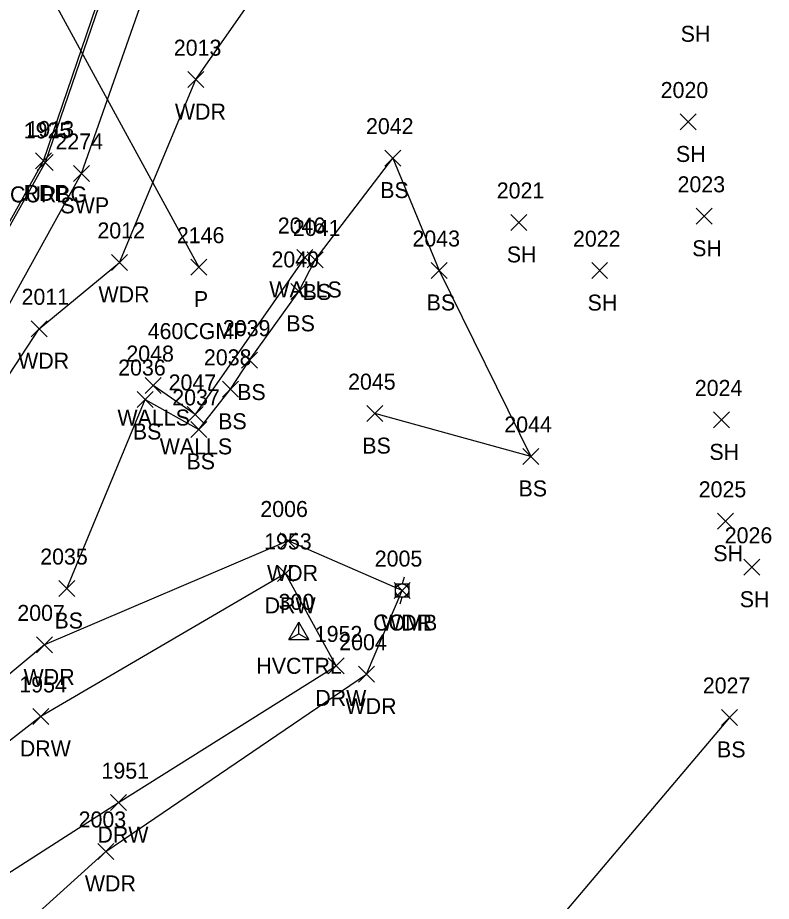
# Model space of a CAD drawing. Extents: x 462930 to 463548, y 29607 to 30453.
# Drawn here: x 463394.45 to 463423.2, y 30175.85 to 30209.54 of the extents above; entities that cross this region are included whole.
import ezdxf

# ---------------------------------------------------------------- set-up
doc = ezdxf.new("R2010")
doc.units = 0
for name, color, linetype in [('C_A', 7, 'Continuous'), ('C_I', 7, 'Continuous'), ('CPSM', 7, 'Continuous'), ('D_A', 7, 'Continuous'), ('D_C', 7, 'Continuous'), ('D_I', 7, 'Continuous'), ('D_TIC', 7, 'Continuous'), ('DCP', 7, 'Continuous'), ('L_A', 7, 'Continuous'), ('L_I', 7, 'Continuous'), ('L_TIC', 7, 'Continuous'), ('LAWA', 7, 'Continuous'), ('LELB', 7, 'Continuous'), ('LWS', 7, 'Continuous'), ('P_A', 7, 'Continuous'), ('P_I', 7, 'Continuous'), ('P_TIC', 7, 'Continuous'), ('PET', 7, 'Continuous'), ('R_A', 7, 'Continuous'), ('R_I', 7, 'Continuous'), ('R_TIC', 7, 'Continuous'), ('RC', 7, 'Continuous'), ('RDW', 7, 'Continuous'), ('RSW', 7, 'Continuous'), ('U_A', 7, 'Continuous'), ('U_I', 7, 'Continuous'), ('UP', 7, 'Continuous')]:
    doc.layers.add(name, color=color, linetype=linetype)

msp = doc.modelspace()

# ---------------------------------------------------------------- linework, layer by layer
at = {"layer": 'CPSM'}
for p, q in [((463404.792, 30185.825), (463405.173, 30186.485)), ((463405.554, 30185.825), (463405.173, 30186.485)), ((463405.173, 30186.045), (463405.173, 30186.485)), ((463404.792, 30185.825), (463405.173, 30186.045)), ((463405.173, 30186.045), (463405.173, 30186.045)), ((463405.173, 30186.045), (463405.554, 30185.825)), ((463404.792, 30185.825), (463405.554, 30185.825))]:
    msp.add_line(p, q, dxfattribs=at)
at = {"layer": 'D_TIC'}
for points in [[(463401.057, 30199.72), (463401.667, 30200.33)], [(463401.667, 30199.72), (463401.057, 30200.33)]]:
    msp.add_lwpolyline(points, dxfattribs=at)
at = {"layer": 'DCP'}
msp.add_lwpolyline([(463390.996, 30218.997), (463401.362, 30200.025)], dxfattribs=at)
at = {"layer": 'L_TIC'}
for points in [[(463400.948, 30206.868), (463401.558, 30207.478)], [(463401.558, 30206.868), (463400.948, 30207.478)], [(463419.715, 30205.254), (463420.325, 30205.864)], [(463420.325, 30205.254), (463419.715, 30205.864)], [(463408.45, 30203.877), (463409.06, 30204.487)], [(463409.06, 30203.877), (463408.45, 30204.487)], [(463420.333, 30201.659), (463420.943, 30202.269)], [(463420.943, 30201.659), (463420.333, 30202.269)], [(463413.264, 30201.425), (463413.874, 30202.035)], [(463413.874, 30201.425), (463413.264, 30202.035)], [(463398.033, 30199.9), (463398.643, 30200.51)], [(463398.643, 30199.9), (463398.033, 30200.51)], [(463405.102, 30200.088), (463405.712, 30200.698)], [(463405.712, 30200.088), (463405.102, 30200.698)], [(463405.49, 30199.994), (463406.1, 30200.604)], [(463406.1, 30199.994), (463405.49, 30200.604)], [(463410.222, 30199.593), (463410.832, 30200.203)], [(463410.832, 30199.593), (463410.222, 30200.203)], [(463416.344, 30199.587), (463416.954, 30200.197)], [(463416.954, 30199.587), (463416.344, 30200.197)], [(463404.871, 30198.797), (463405.481, 30199.407)], [(463405.481, 30198.797), (463404.871, 30199.407)], [(463394.968, 30197.371), (463395.578, 30197.981)], [(463395.578, 30197.371), (463394.968, 30197.981)], [(463402.994, 30196.177), (463403.604, 30196.787)], [(463403.604, 30196.177), (463402.994, 30196.787)], [(463399.31, 30195.206), (463399.92, 30195.816)], [(463399.92, 30195.206), (463399.31, 30195.816)], [(463402.269, 30195.063), (463402.879, 30195.673)], [(463402.879, 30195.063), (463402.269, 30195.673)], [(463399.015, 30194.673), (463399.625, 30195.283)], [(463399.625, 30194.673), (463399.015, 30195.283)], [(463400.923, 30194.106), (463401.533, 30194.716)], [(463401.533, 30194.106), (463400.923, 30194.716)], [(463407.767, 30194.135), (463408.377, 30194.745)], [(463408.377, 30194.135), (463407.767, 30194.745)], [(463420.991, 30193.896), (463421.601, 30194.506)], [(463421.601, 30193.896), (463420.991, 30194.506)], [(463401.061, 30193.536), (463401.671, 30194.146)], [(463401.671, 30193.536), (463401.061, 30194.146)], [(463413.725, 30192.504), (463414.335, 30193.114)], [(463414.335, 30192.504), (463413.725, 30193.114)], [(463421.139, 30190.031), (463421.749, 30190.641)], [(463421.749, 30190.031), (463421.139, 30190.641)], [(463404.46, 30189.281), (463405.07, 30189.891)], [(463405.07, 30189.281), (463404.46, 30189.891)], [(463422.148, 30188.279), (463422.758, 30188.889)], [(463422.758, 30188.279), (463422.148, 30188.889)], [(463396.026, 30187.467), (463396.636, 30188.077)], [(463396.636, 30187.467), (463396.026, 30188.077)], [(463408.808, 30187.39), (463409.418, 30188)], [(463409.418, 30187.39), (463408.808, 30188)], [(463395.176, 30185.32), (463395.786, 30185.93)], [(463395.786, 30185.32), (463395.176, 30185.93)], [(463407.454, 30184.202), (463408.064, 30184.812)], [(463408.064, 30184.202), (463407.454, 30184.812)], [(463421.295, 30182.553), (463421.905, 30183.163)], [(463421.905, 30182.553), (463421.295, 30183.163)], [(463397.514, 30177.445), (463398.124, 30178.055)], [(463398.124, 30177.445), (463397.514, 30178.055)]]:
    msp.add_lwpolyline(points, dxfattribs=at)
at = {"layer": 'LAWA'}
msp.add_lwpolyline([(463387.88, 30168.775), (463397.819, 30177.75), (463407.759, 30184.507), (463409.113, 30187.695), (463404.765, 30189.586), (463395.481, 30185.625), (463385.697, 30177.467), (463383.154, 30179.845), (463389.311, 30188.588), (463395.273, 30197.676), (463398.338, 30200.205), (463401.253, 30207.173), (463406.706, 30214.979), (463411.487, 30213.228), (463413.614, 30212.548), (463416.075, 30212.295), (463420.44, 30211.542)], dxfattribs=at)
at = {"layer": 'LELB'}
for points in [[(463396.331, 30187.772), (463399.32, 30194.978), (463401.366, 30193.841), (463402.574, 30195.368), (463403.299, 30196.482), (463405.176, 30199.102), (463405.795, 30200.299), (463408.755, 30204.182), (463410.527, 30199.898), (463414.03, 30192.809), (463408.072, 30194.44)], [(463421.6, 30182.858), (463413.289, 30173.026), (463407.678, 30171.347), (463399.369, 30168.562), (463394.168, 30167.856), (463387.304, 30164.976), (463384.785, 30156.391), (463383.903, 30152.112)]]:
    msp.add_lwpolyline(points, dxfattribs=at)
at = {"layer": 'LWS'}
msp.add_lwpolyline([(463405.407, 30200.393), (463401.228, 30194.411), (463399.615, 30195.511)], dxfattribs=at)
at = {"layer": 'P_TIC'}
for points in [[(463395.133, 30203.767), (463395.743, 30204.377)], [(463395.743, 30203.767), (463395.133, 30204.377)]]:
    msp.add_lwpolyline(points, dxfattribs=at)
at = {"layer": 'PET'}
msp.add_lwpolyline([(463357.128, 30146.779), (463364.23, 30160.089), (463372.211, 30170.687), (463380.439, 30181.089), (463388.986, 30192.495), (463395.438, 30204.072), (463399.65, 30216.413), (463402.389, 30229.411), (463403.525, 30242.02), (463404.007, 30246.74), (463403.926, 30248.538), (463404.123, 30251.434)], dxfattribs=at)
at = {"layer": 'R_TIC'}
for points in [[(463395.201, 30203.713), (463395.811, 30204.323)], [(463395.811, 30203.713), (463395.201, 30204.323)], [(463396.582, 30203.294), (463397.192, 30203.904)], [(463397.192, 30203.294), (463396.582, 30203.904)], [(463404.368, 30188.044), (463404.978, 30188.654)], [(463404.978, 30188.044), (463404.368, 30188.654)], [(463406.3, 30184.518), (463406.91, 30185.128)], [(463406.91, 30184.518), (463406.3, 30185.128)], [(463395.031, 30182.591), (463395.641, 30183.201)], [(463395.641, 30182.591), (463395.031, 30183.201)], [(463397.992, 30179.305), (463398.602, 30179.915)], [(463398.602, 30179.305), (463397.992, 30179.915)]]:
    msp.add_lwpolyline(points, dxfattribs=at)
at = {"layer": 'RC'}
msp.add_lwpolyline([(463403.888, 30243.164), (463403.731, 30243.164), (463403.598, 30241.759), (463402.492, 30229.375), (463399.74, 30216.359), (463395.506, 30204.018), (463389.016, 30192.435), (463380.487, 30181.016), (463372.297, 30170.609), (463364.316, 30160.034), (463357.246, 30146.767)], dxfattribs=at)
at = {"layer": 'RDW'}
msp.add_lwpolyline([(463370.611, 30158.273), (463377.737, 30164.866), (463387.605, 30172.767), (463398.297, 30179.61), (463406.605, 30184.823), (463404.673, 30188.349), (463395.336, 30182.896), (463385.655, 30175.354), (463377.627, 30169.204)], dxfattribs=at)
at = {"layer": 'RSW'}
msp.add_lwpolyline([(463365.586, 30159.156), (463373.394, 30169.643), (463381.656, 30180.281), (463390.273, 30191.668), (463396.887, 30203.599), (463401.229, 30215.977), (463404.093, 30229.321), (463404.817, 30241.819)], dxfattribs=at)
at = {"layer": 'UP'}
for p, q in [((463409.189, 30188.203), (463409.113, 30187.949)), ((463408.859, 30187.441), (463408.859, 30187.949)), ((463408.859, 30187.949), (463409.367, 30187.949)), ((463409.113, 30187.695), (463409.113, 30187.695)), ((463409.367, 30187.949), (463409.367, 30187.441)), ((463409.367, 30187.441), (463408.859, 30187.441)), ((463409.037, 30187.187), (463409.113, 30187.441))]:
    msp.add_line(p, q, dxfattribs=at)
msp.add_circle((463409.113, 30187.695), 0.254, dxfattribs=at)

# ---------------------------------------------------------------- texts
at = {"layer": 'C_A'}
msp.add_text('HVCTRL', height=0.6096, dxfattribs=at).set_placement((463403.555, 30184.521))
at = {"layer": 'C_I'}
msp.add_text('300', height=0.6096, dxfattribs=at).set_placement((463404.403, 30186.959))
at = {"layer": 'D_A'}
msp.add_text('P', height=0.61, dxfattribs=at).set_placement((463401.172, 30198.501))
at = {"layer": 'D_C'}
msp.add_text('460CGMP', height=0.6096, dxfattribs=at).set_placement((463399.411, 30197.282))
at = {"layer": 'D_I'}
msp.add_text('2146', height=0.6096, dxfattribs=at).set_placement((463400.524, 30200.939))
at = {"layer": 'L_A'}
for s, p in [('SH', (463419.738, 30208.617)), ('WDR', (463400.449, 30205.649)), ('SH', (463419.559, 30204.035)), ('BS', (463408.28, 30202.658)), ('SH', (463413.108, 30200.206)), ('SH', (463420.177, 30200.44)), ('WALLS', (463404.049, 30198.869)), ('WDR', (463397.534, 30198.681)), ('BS', (463405.32, 30198.775)), ('BS', (463410.052, 30198.374)), ('SH', (463416.188, 30198.368)), ('BS', (463404.701, 30197.578)), ('WDR', (463394.469, 30196.152)), ('BS', (463402.824, 30194.958)), ('WALLS', (463398.257, 30193.987)), ('BS', (463402.099, 30193.844)), ('BS', (463398.845, 30193.454)), ('WALLS', (463399.87, 30192.887)), ('BS', (463407.597, 30192.916)), ('SH', (463420.835, 30192.677)), ('BS', (463400.891, 30192.317)), ('BS', (463413.555, 30191.285)), ('SH', (463420.983, 30188.812)), ('WDR', (463403.961, 30188.062)), ('SH', (463421.992, 30187.06)), ('BS', (463395.856, 30186.248)), ('WDR', (463408.309, 30186.171)), ('WDR', (463394.677, 30184.101)), ('WDR', (463406.955, 30182.983)), ('BS', (463421.125, 30181.334)), ('WDR', (463397.015, 30176.226))]:
    msp.add_text(s, height=0.6096, dxfattribs=at).set_placement(p)
at = {"layer": 'L_I'}
for s, p in [('2013', (463400.408, 30208.087)), ('2020', (463418.976, 30206.473)), ('2042', (463407.737, 30205.096)), ('2023', (463419.62, 30202.878)), ('2021', (463412.724, 30202.644)), ('2046', (463404.373, 30201.307)), ('2041', (463404.95, 30201.213)), ('2012', (463397.493, 30201.119)), ('2043', (463409.509, 30200.812)), ('2022', (463415.631, 30200.806)), ('2040', (463404.132, 30200.016)), ('2011', (463394.601, 30198.59)), ('2039', (463402.279, 30197.396)), ('2048', (463398.597, 30196.425)), ('2038', (463401.556, 30196.282)), ('2036', (463398.286, 30195.892)), ('2047', (463400.21, 30195.325)), ('2045', (463407.054, 30195.354)), ('2024', (463420.278, 30195.115)), ('2037', (463400.348, 30194.755)), ('2044', (463413.012, 30193.723)), ('2025', (463420.426, 30191.25)), ('2006', (463403.707, 30190.5)), ('2026', (463421.419, 30189.498)), ('2035', (463395.313, 30188.686)), ('2005', (463408.071, 30188.609)), ('2007', (463394.439, 30186.539)), ('2004', (463406.717, 30185.421)), ('2027', (463420.582, 30183.772)), ('2003', (463396.777, 30178.664))]:
    msp.add_text(s, height=0.6096, dxfattribs=at).set_placement(p)
at = {"layer": 'P_A'}
msp.add_text('RDP', height=0.6096, dxfattribs=at).set_placement((463394.672, 30202.548))
at = {"layer": 'P_I'}
msp.add_text('1913', height=0.6096, dxfattribs=at).set_placement((463394.79, 30204.986))
at = {"layer": 'R_A'}
for s, p in [('CURBG', (463394.16, 30202.494)), ('SWP', (463396.083, 30202.075)), ('DRW', (463403.871, 30186.825)), ('DRW', (463405.803, 30183.299)), ('DRW', (463394.534, 30181.372)), ('DRW', (463397.495, 30178.086))]:
    msp.add_text(s, height=0.6096, dxfattribs=at).set_placement(p)
at = {"layer": 'R_I'}
for s, p in [('1925', (463394.685, 30204.932)), ('2274', (463395.893, 30204.513)), ('1953', (463403.852, 30189.263)), ('1952', (463405.784, 30185.737)), ('1954', (463394.515, 30183.81)), ('1951', (463397.649, 30180.524))]:
    msp.add_text(s, height=0.6096, dxfattribs=at).set_placement(p)
at = {"layer": 'U_A'}
msp.add_text('COMB', height=0.6096, dxfattribs=at).set_placement((463408.011, 30186.171))
at = {"layer": 'U_I'}
msp.add_text('2005', height=0.6096, dxfattribs=at).set_placement((463408.071, 30188.609))

doc.saveas('drawing.dxf')
